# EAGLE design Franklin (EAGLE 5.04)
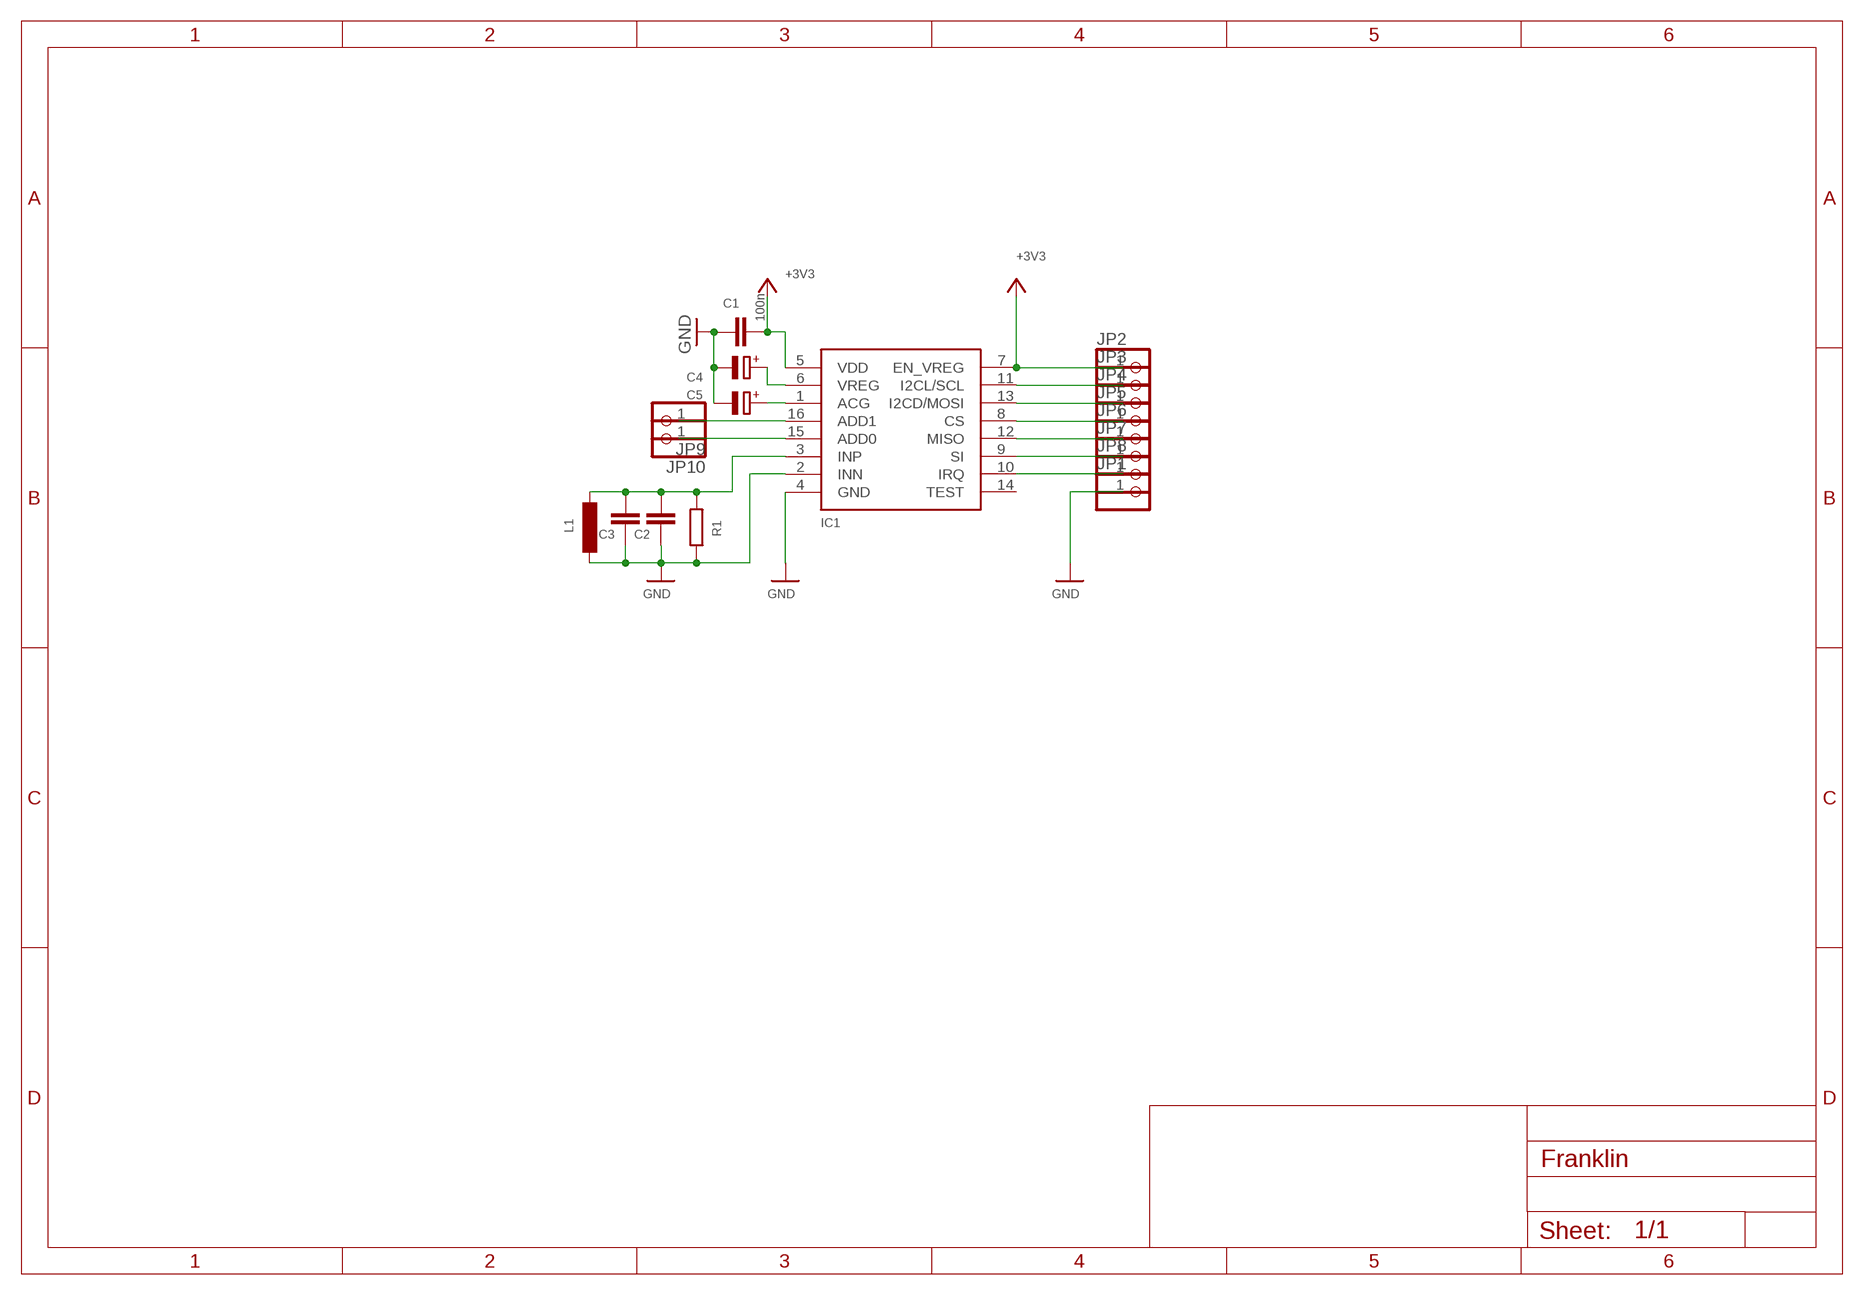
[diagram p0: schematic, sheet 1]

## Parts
C1  100n  C-EUC0805  [C0805]
C2  C-EUC0805  [C0805]
C3  C-EUC0805  [C0805]
C4  CPOL-EUA/3216-18R  [A/3216-18R]
C5  CPOL-EUA/3216-18R  [A/3216-18R]
IC1  AS3935  [QFN-16_4X4]
JP1  PINHD-1X1  [1X01]
JP2  PINHD-1X1  [1X01]
JP3  PINHD-1X1  [1X01]
JP4  PINHD-1X1  [1X01]
JP5  PINHD-1X1  [1X01]
JP6  PINHD-1X1  [1X01]
JP7  PINHD-1X1  [1X01]
JP8  PINHD-1X1  [1X01]
JP9  PINHD-1X1  [1X01]
JP10  PINHD-1X1  [1X01]
L1  L-EU0207/10  [0207/10]
R1  R-EU_R0805  [R0805]

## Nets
+3V3: C1.2 IC1.5(VDD) IC1.7(EN_VREG) JP2.1
GND: C1.1 C2.1 C3.1 C4.- C5.- IC1.2(INN) IC1.4(GND) JP1.1 L1.2 R1.1
N$1: IC1.10(IRQ) JP8.1
N$3: C2.2 C3.2 IC1.3(INP) L1.1 R1.2
N$4: IC1.12(MISO) JP6.1
N$5: IC1.8(CS) JP5.1
N$6: IC1.13(I2CD/MOSI) JP4.1
N$7: IC1.11(I2CL/SCL) JP3.1
N$8: IC1.15(ADD0) JP10.1
N$9: IC1.16(ADD1) JP9.1
N$10: C5.+ IC1.1(ACG)
N$11: C4.+ IC1.6(VREG)
N$12: IC1.9(SI) JP7.1
Unconnected: IC1.14(TEST)

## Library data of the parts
C1-C3 = rcl:C-EU: CAPACITOR, European symbol
C4 C5 = rcl:CPOL-EU: POLARIZED CAPACITOR, European symbol
IC1 = AMESYS:AS3935
JP1-JP10 = pinhead:PINHD-1X1: PIN HEADER
L1 = rcl:L-EU: INDUCTOR, European symbol
R1 = rcl:R-EU_: RESISTOR, European symbol

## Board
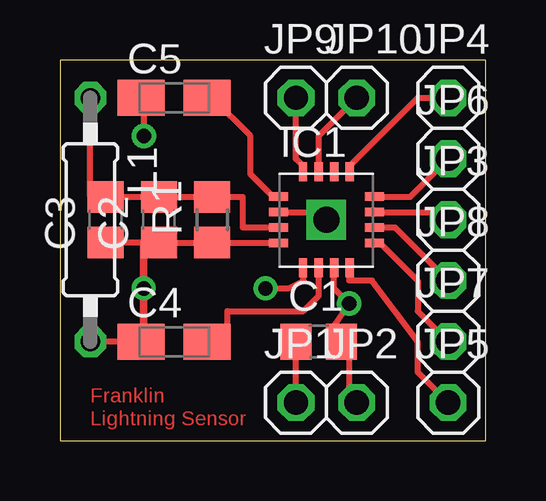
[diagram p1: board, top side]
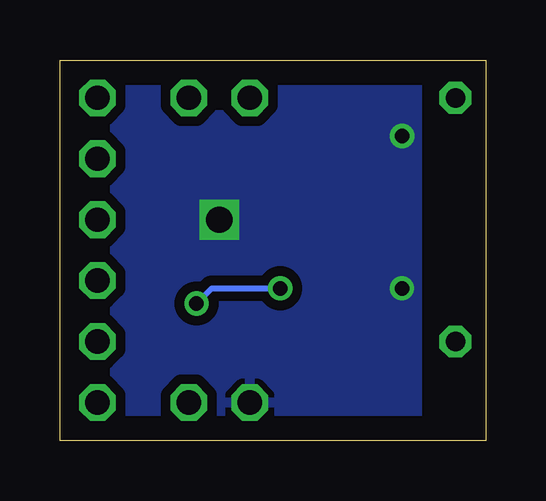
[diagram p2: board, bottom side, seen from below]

Size 17.76 x 15.86 mm. Coordinates in mm from the lower left corner, seen from the top.
Outline: 0,0 17.76,0 17.76,15.86 0,15.86 0,0
Copper layers (1*16): Top 0.035mm / dielectric 1.5mm / Bottom 0.035mm
Design rules "default": minimum track width 10mil, minimum drill 24mil, track to track 8mil, track to pad 8mil, pad to pad 8mil, via to via 8mil, smd to smd 8mil, copper to edge 40mil, drill to drill 8mil, minimum pad ring 10mil, minimum via ring 8mil, stop-mask expansion 4mil, vias tented up to drill 0mil, thermal gap 10mil

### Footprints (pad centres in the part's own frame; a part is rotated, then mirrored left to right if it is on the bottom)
C0805 = smd 1.3 x 1.5: 1 -0.95,0; 2 0.95,0
A/3216-18R = smd 1.95 x 1.5: + 1.375,0; - -1.375,0
QFN-16_4X4 = smd 0.8 x 0.35: 1 -2,0.975; 2 -2,0.325; 3 -2,-0.325; 4 -2,-0.975; 9 2,-0.975; 10 2,-0.325; 11 2,0.325; 12 2,0.975 | smd 0.35 x 0.8: 5 -0.975,-2; 6 -0.325,-2; 7 0.325,-2; 8 0.975,-2; 13 0.975,2; 14 0.325,2; 15 -0.325,2; 16 -0.975,2
1X01 = drill 1.016 octagon: 1 0,0
0207/10 = drill 0.813 octagon: 1 -5.08,0; 2 5.08,0
R0805 = smd 1.3 x 1.5: 1 -0.95,0; 2 0.95,0

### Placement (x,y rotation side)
C1  10.79,4.13 0 top
C2  4.13,9.21 90 top
C3  1.91,9.21 90 top
C4  4.76,4.13 0 top
C5  4.76,14.29 0 top
IC1  11.11,9.21 0 top
JP1  9.84,1.59 0 top
JP2  12.38,1.59 0 top
JP3  16.19,9.21 0 top
JP4  16.19,14.29 0 top
JP5  16.19,1.59 0 top
JP6  16.19,11.75 0 top
JP7  16.19,4.13 0 top
JP8  16.19,6.67 0 top
JP9  9.84,14.29 0 top
JP10  12.38,14.29 0 top
L1  1.27,9.21 270 top
R1  6.35,9.21 90 top

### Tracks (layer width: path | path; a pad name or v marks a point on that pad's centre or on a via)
+3V3  (via drill 0.6)
  Top 0.254: 10.16,6.99 IC1.5 10.16,7.3 10.16,6.67 9.53,6.35 v8.57,6.35 | 11.43,6.99 11.43,7.3 IC1.7 11.43,6.99 | 11.43,6.99 11.43,6.35 v12.06,5.72 11.43,4.76 C1.2 12.06,3.49 12.06,2.22 JP2.1
  Bottom 0.254: v8.57,6.35 11.43,6.35 v12.06,5.72
GND  (via drill 0.6, 0.61, 1.1 pad 1.42)
  Top 0.254: 6.03,8.25 8.89,8.25 IC1.4 | 8.89,9.52 IC1.2 9.21,9.52 10.48,9.52 v11.11,9.21 | 3.49,8.25 2.22,8.25 C3.1 | 3.49,4.13 C4.- L1.2 | 3.49,8.25 6.03,8.25 | 6.03,8.25 R1.1 | 3.49,8.25 C2.1 | v3.49,12.7 3.49,14.29 C5.- | C1.1 9.84,3.49 JP1.1
  Top 0.305: 3.49,8.25 v3.49,6.35 3.49,4.23 C4.- | IC1.4 9.14,8.25
  pour Bottom (isolate 0.406): 2.86,15.88 17.78,15.88 17.78,0 2.86,0
N$1
  Top 0.254: JP8.1 13.97,8.89 13.33,8.89 IC1.10
N$3
  Top 0.254: 1.27,10.16 3.49,10.16 | 3.49,10.16 6.03,10.16 7.62,10.16 7.62,8.89 9.21,8.89 IC1.3 | 3.49,10.16 C2.2 | 1.27,10.16 L1.1 | C3.2 1.27,10.16
  Top 0.305: 6.03,10.16 R1.2
N$4
  Top 0.254: JP6.1 14.6,10.16 13.33,10.16 IC1.12
N$5
  Top 0.254: JP5.1 14.92,2.86 14.92,4.13 13.02,6.67 12.06,6.67 IC1.8
N$6
  Top 0.254: JP4.1 14.92,14.29 12.06,11.43 IC1.13
N$7
  Top 0.254: JP3.1 16.19,9.52 13.33,9.52 IC1.11
N$8
  Top 0.254: JP10.1 10.8,12.7 10.8,11.43 IC1.15
N$9
  Top 0.254: JP9.1 9.84,11.75 10.16,11.43 IC1.16
N$10
  Top 0.254: IC1.1 8.89,10.16 7.94,11.11 7.94,12.7 6.35,14.29 C5.+
N$11
  Top 0.254: 10.8,7.3 IC1.6 10.8,6.99 10.8,6.03 10.16,5.4 6.98,5.4 6.98,4.76 C4.+
  Top 0.305: IC1.6
N$12
  Top 0.254: JP7.1 14.92,5.4 14.92,6.67 13.33,8.25 IC1.9

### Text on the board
Top: Franklin | Lightning Sensor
